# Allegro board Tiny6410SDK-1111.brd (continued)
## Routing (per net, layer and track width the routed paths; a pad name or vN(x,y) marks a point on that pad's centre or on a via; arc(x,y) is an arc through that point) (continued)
TXD2: length 230.1
  TOP w0.203: v1(78.32,95.63) 78.87,95.08 79.96,95.08 80.84,94.2 96.62,94.2 99.95,97.53 99.95,98.17 100.58,98.81 U1.10 ; v1(90.93,62.1) 89.87,62.1 89.77,62.2 71.75,62.2 66.06,67.89 26.09,67.89 24.31,66.12 20.21,66.12 15.75,61.65 15.75,60.25 TINY6410.B11 ; v1(78.87,86.23) 79.17,85.93 109.28,85.93 109.58,86.23 111.84,86.23 113.58,87.97 114.21,87.97 115.27,89.03 116.1,89.03 117.07,89.99 117.86,89.99 119,91.14 CON5.11
  BOTTOM w0.203: v1(90.93,62.1) 89.79,62.1 86,65.89 86,78.82 83.74,81.08 83.74,81.99 79.5,86.23 v1(78.87,86.23) 79.02,86.38 79.02,94.85 78.32,95.54 v1(78.32,95.63) 78.32,96.05 69.42,104.95 69.42,105.87 66.73,108.56 58.6,108.56 56.95,110.21 48.77,110.21 47.02,111.96 CON3.1
TXD3: length 169.2
  TOP w0.203: v1(90.93,61.05) 90.56,61.05 89.96,60.45 75.02,60.45 74.08,61.39 71.41,61.39 65.72,67.08 26.43,67.08 24.65,65.3 23.64,65.3 21.11,65.3 17.78,61.98 17.78,60.22 TINY6410.B13
  BOTTOM w0.203: CON4.1 35.97,112.27 42.3,105.94 64.8,105.94 66.22,104.53 66.22,87.96 83.19,70.99 83.19,67.56 89.14,61.6 89.14,61.11 89.53,60.72 90.23,60.72 90.56,61.05 v1(90.93,61.05)
USB_D+: length 50
  TOP w0.203: v1(110.11,51.26) 109.84,51.52 U6.6
  BOTTOM w0.203: v1(110.11,51.26) 110.72,51.87 111.13,51.87 113.54,54.28 113.54,66.43 108.41,71.56 108.41,85.8 112.01,89.41 112.01,92.84 111.35,93.5 CON5.4
USB_D-: length 46.4
  TOP w0.203: U6.5 109.96,52.17 v1(110.11,52.32)
  BOTTOM w0.203: CON5.3 111.38,91.12 111.38,89.53 107.95,86.11 107.95,71.37 113.09,66.24 113.09,54.43 110.99,52.32 v1(110.11,52.32)
USBDN: length 125.6
  TOP w0.203: TINY6410.A32 36.8,101.2 36.8,96.68 45.14,88.34 48.44,88.34 50.93,85.85 56.52,85.85 58.07,84.29 72.1,84.29 72.55,83.85 76.03,80.37 107.86,80.37 108.25,80.75 109.89,80.75 110.26,80.37 v1(110.24,79.79) ; v1(122.05,49) 122.02,49.02 121.03,49.02 120.93,48.92 R16.1
  BOTTOM w0.203: v1(110.24,79.79) 110.49,79.54 110.49,77.09 115.7,71.88 115.7,52.45 118.9,49.25 121.21,49.25 121.46,49 v1(122.05,49)
USBDP: length 125.3
  TOP w0.203: TINY6410.A34 37.2,101.2 37.2,96.85 45.3,88.75 48.61,88.75 51.1,86.26 56.68,86.26 58.24,84.7 72.27,84.7 72.83,84.14 76.2,80.77 107.7,80.77 108.08,81.15 110.06,81.15 110.55,80.66 110.79,80.65 110.89,80.65 110.93,80.6 111.18,80.33 v1(111.15,79.75) ; R17.1 120.93,50.01 121.28,49.66 121.79,49.66 v1(122.05,49.91)
  BOTTOM w0.203: v1(111.15,79.75) 111,79.6 111,77.16 116.1,72.05 116.1,52.62 119.07,49.66 121.21,49.66 121.46,49.91 v1(122.05,49.91)
USBH_D+: length 9
  TOP w0.203: U6.26 116.45,53.47 117.47,52.45 117.47,51.31 118.62,50.16 R17.2 R79.2 R54.1
USBH_D-: length 7.9
  TOP w0.203: R80.2 R16.2 119.35,48.67 117.07,50.95 117.07,52.1 116.34,52.82 U6.25
VCLK: length 192.2
  TOP w0.203: v1(126.62,69.47) 127.81,68.28 130.68,68.28 132.26,66.69 LCD1.36 ; LCD3.36 175.99,92.93 173.48,90.43 LCD2.36 168.57,90.43 167.57,91.43 160.46,91.43 159.9,90.86 149.99,90.86 146.99,87.86 130.73,87.86 126.49,83.62 125.92,83.62 125.77,83.46 123.6,83.46 122.86,82.73 v1(122.79,82.73) 122.53,82.47 115.3,82.47 111.57,78.74 76.91,78.74 71.76,83.89 41.99,83.89 29.02,96.86 29.02,103.02 TINY6410.A25
  BOTTOM w0.203: v1(122.79,82.73) 122.81,82.71 122.81,72.64 125.98,69.47 v1(126.62,69.47)
VD0: length 45
  TOP w0.203: LCD3.3 176.93,62.04 175.6,62.04 173.28,64.36 173.28,73.79 173.14,73.92 LCD2.3 165.11,73.92 159.69,68.5 149.71,68.5 148.77,67.56 LCD1.3
VD1: length 47.4
  TOP w0.203: LCD2.4 164.96,74.42 v1(164.7,74.68) 163.45,74.68 157.68,68.91 149.55,68.91 148.27,67.63 LCD1.4
  BOTTOM w0.203: v1(164.7,74.68) 164.7,72.94 175.99,61.65 LCD3.4
VD2: length 209.4
  TOP w0.203: v1(150.24,85.84) 150.24,85.83 148.41,85.83 147.92,85.34 132.97,85.34 128.07,80.44 117.14,80.44 113.41,76.71 76.07,76.71 70.92,81.86 39.94,81.86 24.49,97.31 24.49,101.51 TINY6410.A20 ; LCD1.5 147.77,68.01 149.25,69.49 150.77,69.49 v1(151,69.72) 151.28,70 158.01,70 163.83,75.82 v1(165.23,75.82) 166.12,74.92 LCD2.5
  BOTTOM w0.203: v1(151,69.72) 150.72,70 150.72,70.55 150.24,71.04 v1(150.24,85.84) ; v1(165.23,75.82) 165.48,75.56 165.48,73.15 174.62,64.01 176.3,64.01 177.33,62.98 LCD3.5
VD3: length 207
  TOP w0.203: LCD3.6 173.71,65.26 173.71,74.96 173.24,75.42 LCD2.6 166.66,75.42 165.61,76.48 163.47,76.48 157.4,70.41 150.32,70.41 v1(150.06,70.15) 149.32,70.15 147.27,68.1 LCD1.6 ; v1(149.48,85.09) 149.14,85.09 148.99,85.24 148.44,85.24 148.14,84.94 133.14,84.94 128.23,80.04 117.31,80.04 113.58,76.3 75.9,76.3 70.75,81.45 39.69,81.45 38.54,82.6 38.43,82.6 24.05,96.98 24.05,100.46 23.08,101.43 23.08,103.08 TINY6410.A19
  BOTTOM w0.203: v1(149.48,85.09) 149.73,84.84 149.73,70.48 v1(150.06,70.15)
VD4: length 209.5
  TOP w0.203: TINY6410.A18 22,96.75 36.55,82.19 38.37,82.19 39.52,81.04 70.58,81.04 75.73,75.9 113.75,75.9 117.48,79.63 128.4,79.63 133.31,84.53 148.31,84.53 148.36,84.58 v1(148.72,84.58) ; LCD1.7 146.77,68.53 v1(148.75,70.51) 149.05,70.82 156.92,70.82 163.12,77.01 v1(166.37,77.01) 167.46,75.92 LCD2.7
  BOTTOM w0.203: v1(166.37,77.01) 166.45,76.94 166.45,73.94 174.35,66.04 176.26,66.04 177.32,64.98 LCD3.7 ; v1(148.75,70.51) 148.75,70.85 149.28,71.37 149.28,84.02 v1(148.72,84.58)
VD5: length 212.1
  TOP w0.203: v1(147.57,83.06) 146.51,84.12 133.47,84.12 128.57,79.22 117.65,79.22 113.92,75.49 75.56,75.49 70.41,80.64 37.35,80.64 21.09,96.9 21.09,103.09 TINY6410.A17 ; LCD1.8 146.27,69.18 147.32,70.23 147.32,70.27 v1(147.35,70.3) 147.35,70.36 148.21,71.22 156.69,71.22 163.19,77.72 v1(164.62,77.72) 166.71,77.72 168.01,76.42 LCD2.8
  BOTTOM w0.203: v1(164.62,77.72) 164.72,77.72 165.91,76.53 165.91,73.61 174.54,64.98 LCD3.8 ; v1(147.35,70.3) 147.35,70.39 147.96,70.99 147.96,78.06 147.8,78.21 147.8,81.69 147.57,81.92 v1(147.57,83.06)
VD6: length 207.7
  TOP w0.203: v1(146.56,83.06) 145.9,83.72 133.64,83.72 128.74,78.82 117.82,78.82 114.09,75.08 75.39,75.08 70.25,80.23 36.99,80.23 20.29,96.93 20.29,101.71 TINY6410.A16 ; LCD1.9 145.77,69.95 v1(146.94,71.12) 147.45,71.63 156.34,71.63 163.09,78.38 166.98,78.38 v1(167.51,77.85) 168.44,76.92 LCD2.9
  BOTTOM w0.203: v1(146.94,71.12) 147.32,71.5 147.32,81.31 146.56,82.07 v1(146.56,83.06) ; v1(167.51,77.85) 174.57,70.79 174.57,69.07 175.6,68.04 176.26,68.04 177.32,66.98 LCD3.9
VD7: length 206.8
  TOP w0.203: LCD3.10 174.12,68.85 174.12,75.13 173.69,75.56 173.69,76.38 173.33,76.73 173.33,77.24 173.14,77.42 LCD2.10 168.96,77.42 167.41,78.97 162.53,78.97 155.7,72.14 146.71,72.14 v1(146.56,71.98) 145.27,70.69 LCD1.10 ; TINY6410.A15 19.09,103.09 19.09,101.29 19.53,100.84 19.53,96.8 36.51,79.82 70.08,79.82 75.23,74.68 114.25,74.68 117.99,78.41 128.91,78.41 133.3,82.8 145.16,82.8 v1(145.41,83.06)
  BOTTOM w0.203: v1(146.56,71.98) 146.56,81.11 145.41,82.25 v1(145.41,83.06)
VD8: length 49.2
  TOP w0.203: LCD1.12 144.27,71.06 145.85,72.64 155.64,72.64 162.37,79.38 168.06,79.38 168.64,78.8 170.05,78.8 170.24,78.61 170.6,78.61 170.78,78.42 LCD2.12 173.27,78.42 173.74,77.96 173.74,76.91 174.09,76.56 174.09,75.74 174.52,75.31 174.52,70.45 LCD3.12
VD9: length 52.1
  TOP w0.203: LCD3.13 177.05,70.04 175.6,70.04 174.93,70.71 174.93,75.49 174.5,75.92 174.5,76.73 174.14,77.09 174.14,78.36 173.58,78.92 LCD2.13 170.86,78.92 170.76,79.02 170.4,79.02 170.22,79.2 168.81,79.2 168.23,79.78 162.2,79.78 155.57,73.15 154.75,73.15 154.73,73.13 145.75,73.13 143.77,71.15 LCD1.13
VD10: length 199.7
  TOP w0.203: TINY6410.A14 18,101.58 19.05,100.53 19.05,96.52 36.15,79.42 69.91,79.42 75.06,74.27 114.6,74.27 118.33,78 134.87,78 135.51,78.64 140.01,78.64 140.32,78.33 141.22,78.33 141.46,78.57 v1(143.76,78.57) ; LCD1.14 143.27,71.59 143.92,72.24 v1(143.92,72.29) 145.16,73.53 154.56,73.53 161.21,80.19 168.4,80.19 168.98,79.61 170.39,79.61 170.57,79.42 LCD2.14 173.74,79.42 174.55,78.61 174.55,77.34 175.05,76.84 175.05,76.31 175.44,75.92 176.38,75.92 176.93,75.37 176.93,71.92 LCD3.14
  BOTTOM w0.203: v1(143.76,78.57) 144.02,78.32 144.02,72.39 v1(143.92,72.29)
VD11: length 206.8
  TOP w0.203: v1(142.8,77.17) 136.53,77.17 136.15,77.55 118.45,77.55 114.76,73.86 74.89,73.86 69.74,79.01 35.8,79.01 18.44,96.37 18.44,99.85 17.09,101.2 17.09,103.09 TINY6410.A13 ; LCD2.15 170.65,79.92 170.55,80.02 169.16,80.02 168.43,80.75 164.67,80.75 v1(164.57,80.85) 161.16,80.85 160.12,79.81 159.94,79.81 154.18,74.04 144.7,74.04 142.95,72.29 v1(142.93,72.29) 142.77,72.13 LCD1.15
  BOTTOM w0.203: v1(142.93,72.29) 142.98,72.29 143.38,72.69 143.38,76.44 142.8,77.02 v1(142.8,77.17) ; v1(164.57,80.85) 165.33,80.09 166.29,80.09 174.34,72.04 176.38,72.04 177.32,72.98 LCD3.15
VD12: length 202.3
  TOP w0.203: TINY6410.A12 16,96.14 33.54,78.6 69.57,78.6 74.72,73.46 114.93,73.46 118.62,77.14 135.98,77.14 136.36,76.76 142.13,76.76 v1(142.68,76.2) ; LCD1.16 142.26,67.54 142.24,67.56 142.24,72.8 142.65,73.2 v1(142.68,73.2) 144.03,74.55 154.11,74.55 161.1,81.53 v1(165.38,81.53) 165.55,81.36 168.46,81.36 169.39,80.42 LCD2.16
  BOTTOM w0.203: v1(165.38,81.53) 166.41,80.51 166.46,80.51 173.99,72.98 LCD3.16 ; v1(142.68,73.2) v1(142.68,76.2)
VD13: length 205.7
  TOP w0.203: v1(141.73,76.1) 141.48,76.35 136.09,76.35 135.71,76.73 118.78,76.73 115.1,73.05 74.55,73.05 69.4,78.2 32.93,78.2 15.09,96.04 15.09,103.09 TINY6410.A11 ; LCD1.17 141.76,73.59 v1(141.86,73.69) 141.86,73.74 142.65,74.52 143.09,74.52 143.63,75.06 154.04,75.06 161.31,82.32 167.25,82.32 v1(167.55,82.02) 167.62,82.02 167.75,81.89 168.5,81.89 169.47,80.92 LCD2.17
  BOTTOM w0.203: LCD3.17 177.98,74.98 176.92,73.92 175.72,73.92 175.05,74.59 175.05,74.59 167.62,82.02 v1(167.55,82.02) ; v1(141.86,73.69) 141.86,73.82 141.73,73.95 v1(141.73,76.1)
VD14: length 201.3
  TOP w0.203: TINY6410.A10 13.51,101.51 13.51,96.72 32.44,77.79 69.24,77.79 74.38,72.64 115.27,72.64 118.95,76.33 135.51,76.33 136.14,75.69 138.1,75.69 138.89,74.9 141.58,74.9 141.6,74.93 ; LCD2.18 169.65,81.42 168.28,82.8 v1(168.02,82.8) 167.89,82.93 159.13,82.93 151.74,75.54 143.53,75.54 142.92,74.93 141.6,74.93 ; LCD1.18 141.26,73.35 141.2,73.41 141.2,73.96 141.6,74.37 141.6,74.93
  BOTTOM w0.203: v1(168.02,82.8) 168.35,82.47 168.35,81.92 175.29,74.98 LCD3.18
VD15: length 204.2
  TOP w0.203: v1(139.19,75.56) 139.32,75.44 142.41,75.44 142.51,75.54 142.96,75.54 143.36,75.95 151.57,75.95 159.22,83.59 168.18,83.59 169.07,82.7 169.08,82.7 169.86,81.92 LCD2.19 173.09,81.92 174.98,80.04 174.98,78.52 175.58,77.93 177.1,77.93 177.37,77.66 177.37,77.6 LCD3.19 ; TINY6410.A9 13.09,103.09 13.09,96.13 31.83,77.39 69.07,77.39 74.22,72.24 74.55,72.24 115.44,72.24 119.12,75.92 135.2,75.92 135.92,75.21 137.64,75.21 138.81,74.04 v1(139.19,74.04) 140.34,74.04 140.76,73.61 LCD1.19
  BOTTOM w0.203: v1(139.19,75.56) 139.06,75.44 139.06,74.17 v1(139.19,74.04)
VD16: length 58
  TOP w0.203: LCD1.21 139.76,71.82 138.94,72.64 v1(138.94,73.15) ; LCD3.21 176.93,80.04 175.58,80.04 174.24,81.38 174.24,82.76 173.88,83.11 173.34,83.11 173.14,82.92 LCD2.21 170.49,82.92 170.33,83.08 169.26,83.08 168.26,84.08 157.83,84.08 151.57,77.83 139.34,77.83 v1(139.32,77.85)
  BOTTOM w0.203: v1(138.94,73.15) 138.94,73.28 138.3,73.91 138.3,76.83 v1(139.32,77.85)
VD17: length 64
  TOP w0.203: v1(140.59,78.99) 140.97,79.38 150.88,79.38 156.34,84.84 164.97,84.84 v1(165.1,84.96) 165.57,84.49 168.43,84.49 169.43,83.49 170.5,83.49 170.56,83.42 LCD2.22 ; v1(137.92,73.28) 137.92,73.03 139.26,71.68 LCD1.22
  BOTTOM w0.203: v1(140.59,78.99) 140.13,78.99 139.85,78.71 139.17,78.71 137.85,77.39 137.85,73.36 v1(137.92,73.28) ; v1(165.1,84.96) 165.74,84.33 170.69,84.33 175.99,79.02 LCD3.22
VD18: length 209.7
  TOP w0.203: LCD1.23 138.76,71.42 136.65,73.53 v1(136.65,73.66) 136.14,73.66 135.6,74.2 134.78,74.2 134.05,74.93 133.8,75.18 130.31,75.18 129.98,75.51 124.59,75.51 124.21,75.13 118.91,75.13 115.1,71.32 74.56,71.32 68.9,76.98 31.2,76.98 11.56,96.62 11.56,101.56 TINY6410.A8 ; LCD2.23 169.57,83.92 168.6,84.9 168.49,84.92 168.34,85.08 166.55,85.08 166.42,85.22 v1(165.99,85.22) 165.58,85.62 156.55,85.62 150.73,79.81 140,79.81 v1(139.57,79.38)
  BOTTOM w0.203: v1(139.57,79.38) 139.21,79.38 136.4,76.56 136.4,73.91 v1(136.65,73.66) ; LCD3.23 177.05,81.92 175.51,81.92 174.25,83.18 172.46,83.18 170.8,84.84 166.37,84.84 v1(165.99,85.22)
VD19: length 207.9
  TOP w0.203: v1(136.6,79.45) 137.36,80.21 150.56,80.21 156.38,86.03 166.18,86.03 166.72,85.49 168.58,85.49 169.64,84.42 LCD2.24 173.06,84.42 173.96,83.52 174.05,83.52 174.65,82.93 174.65,82.32 LCD3.24 ; TINY6410.A7 11.09,103.09 11.09,96.1 30.73,76.45 68.85,76.45 74.39,70.92 115.27,70.92 119.05,74.7 124.35,74.7 124.43,74.78 133.63,74.78 134.62,73.79 135.38,73.79 v1(137.41,71.75) 138.26,70.91 LCD1.24
  BOTTOM w0.203: v1(136.6,79.45) 136.6,78.82 135.84,78.05 135.84,73.33 v1(137.41,71.75)
VD20: length 208.1
  TOP w0.203: v1(134.75,78.99) 136.37,80.62 150.4,80.62 156.21,86.44 166.35,86.44 166.89,85.89 168.75,85.89 169.72,84.92 LCD2.25 173.15,84.92 174.14,83.93 174.22,83.93 175.05,83.1 175.05,82.59 175.6,82.04 176.38,82.04 176.38,82.04 177.05,82.04 LCD3.25 ; LCD1.25 137.76,70.39 v1(135.13,73.03) 134.62,73.03 133.27,74.37 124.6,74.37 124.52,74.3 119.22,74.3 115.44,70.51 74.22,70.51 68.68,76.05 30.38,76.05 9.68,96.75 9.68,101.68 TINY6410.A6
  BOTTOM w0.203: v1(134.75,78.99) 134.75,78.74 134.24,78.23 134.24,73.91 v1(135.13,73.03)
VD21: length 210.4
  TOP w0.203: LCD3.26 175.21,83.76 175.21,83.86 173.8,85.27 173.38,85.27 173.22,85.43 LCD2.26 169.79,85.43 168.92,86.3 167.06,86.3 166.52,86.84 156.04,86.84 150.23,81.03 135.64,81.03 v1(133.86,79.25) ; TINY6410.A5 9.09,103.09 9.09,96.32 29.84,75.56 68.59,75.56 74.05,70.1 115.6,70.1 119.39,73.89 124.69,73.89 124.77,73.96 133.05,73.96 v1(135.51,71.5) 137.26,69.75 LCD1.26
  BOTTOM w0.203: v1(135.51,71.5) 133.73,73.28 133.73,79.12 v1(133.86,79.25)
VD22: length 211.6
  TOP w0.203: LCD3.27 177.05,84.04 175.6,84.04 173.97,85.67 173.55,85.67 173.3,85.93 LCD2.27 169.87,85.93 169.09,86.71 167.23,86.71 166.68,87.25 155.88,87.25 150.11,81.48 134.19,81.48 133.1,80.39 133.1,79.72 v1(133.05,79.68) ; LCD1.27 136.76,69.12 134.12,71.75 v1(134.11,71.75) 132.31,73.56 124.94,73.56 124.86,73.48 119.56,73.48 115.77,69.7 73.88,69.7 68.42,75.16 29.24,75.16 7.67,96.72 7.67,100.89 8,101.22 TINY6410.A4
  BOTTOM w0.203: v1(133.05,79.68) 133.05,79.61 132.94,79.5 132.94,72.94 134.11,71.77 v1(134.11,71.75)
VD23: length 213.8
  TOP w0.203: LCD1.28 136.26,68.59 v1(134.37,70.48) 131.7,73.15 130.47,73.15 130.39,73.08 119.73,73.08 115.94,69.29 73.71,69.29 68.3,74.7 28.8,74.7 7.08,96.42 7.08,103.08 TINY6410.A3 ; v1(132.08,79.12) 132.08,79.95 134.02,81.89 149.94,81.89 155.71,87.66 166.85,87.66 167.4,87.11 169.25,87.11 169.94,86.43 LCD2.28 173.37,86.43 173.72,86.08 174.89,86.08 LCD3.28
  BOTTOM w0.203: v1(132.08,79.12) 132.28,78.92 132.28,72.57 v1(134.37,70.48)
VDEN: length 195.3
  TOP w0.203: LCD3.33 177.03,90.02 175.51,90.02 174.42,88.93 LCD2.33 168.35,88.93 167.33,89.94 161.04,89.94 160.74,89.64 151.37,89.64 151.13,89.41 150.62,89.41 v1(150.37,89.15) ; LCD1.33 133.76,66.92 130.27,70.41 129.24,70.41 v1(128.68,70.97) ; TINY6410.A21 25.02,103.02 25.02,97.66 40.42,82.26 71.09,82.26 76.24,77.11 112.24,77.11 115.97,80.85 127.3,80.85 v1(127.56,81.1) 127.97,81.1 128.73,81.86 128.77,81.86 132.73,85.83 147.83,85.83 148.75,86.74 v1(150.37,86.74)
  BOTTOM w0.203: v1(150.37,86.74) v1(150.37,89.15) ; v1(127.56,81.1) 127.56,72.01 128.6,70.97 v1(128.68,70.97)
VSYNC: length 191.1
  TOP w0.203: LCD1.34 133.26,66.84 130.26,69.85 v1(128.65,69.85) ; TINY6410.A23 27.02,103.02 27.02,97.19 41.13,83.08 71.43,83.08 76.57,77.93 111.9,77.93 115.64,81.66 125.48,81.66 125.73,81.92 v1(126.36,81.92) 126.36,82.17 126.95,82.76 126.95,82.85 127.71,83.61 127.71,83.64 131.11,87.05 147.33,87.05 150.09,89.81 150.22,89.81 150.46,90.05 160.49,90.05 160.86,90.43 167.42,90.43 168.42,89.43 LCD2.34 173.88,89.43 175.26,90.81 175.82,90.81 LCD3.34
  BOTTOM w0.203: v1(128.65,69.85) 127.91,70.59 127.91,70.89 126.72,72.09 126.72,81.56 v1(126.36,81.92)
WIFI_IO: length 120.1
  TOP w0.203: CON11.11 148.46,96.04 148.46,96.71 147.94,97.23 147.94,97.89 145.63,100.2 112.46,100.2 101.98,89.73 72.45,89.73 71.63,90.55 R18.1 70.27,89.8 68.05,89.8 65.93,91.92 55.14,91.92 48.39,98.68 47.8,98.68 46.84,99.64 45.72,99.64 45.09,100.28 45.09,103.08 TINY6410.A41
WIFI_PD: length 114.7
  TOP w0.203: CON11.12 148.88,97.5 148.35,98.03 148.35,98.06 145.77,100.63 112.31,100.63 101.82,90.14 74.2,90.14 72.26,92.08 R73.1 70.27,91.33 67.1,91.33 66.09,92.33 55.31,92.33 48.56,99.09 48.01,99.09 46.61,100.48 46.61,101.39 TINY6410.A42
X1: length 17.3
  TOP w0.254: 117.86,47.37 117.86,48.9 116.53,50.22 U6.21 ; 117.86,47.37 117.86,47.12 118.11,46.86 ; 117.86,47.37 118.11,47.12 118.11,46.86 ; Y1.2 126.25,47.64 123.42,44.81 120.31,44.81 119.52,45.59 C31.1 118.11,46.86
X2: length 15.5
  TOP w0.254: U6.20 116.2,49.57 116.64,49.13 116.64,49.1 117.22,48.51 117.22,46.37 118.87,44.72 118.87,44.07 C64.1 120.29,44.22 122.05,44.22 122.15,44.32 125.93,44.32 Y1.1

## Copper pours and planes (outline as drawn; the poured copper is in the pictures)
GND on TOP (solid shape): 38.85,22.48 38.86,22.48 38.88,22.47 38.9,22.45 38.91,22.43 38.91,22.34 37.82,21.25 37.82,18.64 32.67,13.49 25.87,13.49 24.85,14.51 30.23,14.51 30.23,17.56 26.67,17.56 26.67,14.51 24.85,14.51 24.79,14.57 24.79,19.91 24.79,19.93 24.8,19.96 24.82,19.99 24.84,20.01 24.87,20.03 24.9,20.04 24.93,20.04 24.97,20.03 25,20.01 25.01,20 25.91,19.1 36.7,19.1 37.11,19.51 37.11,22.42 37.11,22.43 37.12,22.45 37.14,22.47 37.16,22.48 37.17,22.48
GND on TOP (solid shape): 115.97,7.1 116.07,7.13 116.16,7.08 116.92,6.58 117.81,6.78 117.94,6.79 118.01,6.68 118.01,5.89 117.99,5.85 117.94,5.83 117.67,5.83 117.67,3.59 117.66,3.58 112.13,3.58 112.02,3.66 112.04,3.8 112.28,4.04 112.87,4.04 114.63,5.8 114.67,5.8
GND on TOP (solid shape): 135.84,16.24 135.95,16.19 136.06,16.16 136.16,16.07 136.11,15.94 135.94,15.23 136.57,14.86 136.58,14.86 136.61,14.85 137.39,14.08 137.39,13.59 137.31,13.47 137.17,13.5 136.18,13.86 135.32,13.28 135.17,13.21 135.08,13.34 135.08,15.54 135.78,16.24 135.82,16.25
GND on TOP (solid shape): 112.78,11.91 112.79,11.89 113.63,11.16 114.69,11.47 114.83,11.5 114.91,11.38 114.91,10.49 114.99,10.41 114.99,8.54 114.9,8.42 114.76,8.45 112.89,8.31 113.63,6.59 113.73,6.5 113.69,6.37 112.43,5.11 111.84,5.11 111.81,5.07 111.74,5.06 111.7,5.12 111.7,5.83 111.42,5.83 111.37,5.85 111.35,5.89 111.35,8.96 108.59,11.73 108.57,11.76 108.57,11.8 108.62,11.91 108.65,11.93 112.75,11.93
GND on TOP (solid shape): 135.08,12.09 135.17,12.21 135.32,12.15 136.18,11.57 137.17,11.93 137.31,11.96 137.39,11.84 137.39,11.67 135.97,10.25 135.97,8.41 135.95,8.38 135.93,8.37 135.51,6.47 137.41,6.89 137.42,6.91 137.45,6.93 141.55,6.93 141.58,6.91 141.59,6.89 142.23,6.22 143.16,6.24 143.18,6.25 143.22,6.24 144.71,4.75 145.03,4.75 145.08,4.73 145.1,4.69 145.1,4.13 145.08,4.08 145.03,4.06 144.65,4.06 143.98,4.72 135.29,4.72 134.63,4.06 133.99,4.06 133.94,4.08 133.92,4.13 133.92,5.66 134.8,6.53 134.8,9.24 134.47,9.57 134.47,10.65 135.08,11.26
GND on TOP (solid shape): outline of 26657 points within 0.51,0.51 179.49,129.49
GND on TOP: 128.78,43.43 126.24,40.65 123.7,43.43 123.7,49.28 126.24,52.29 128.78,49.28
GND on TOP: 110.49,82.68 111.38,82.68 112.39,81.66 112.39,81.15 112.14,80.9 111.38,80.9 111,81.28 111,81.66 110.36,82.3 110.36,82.55
GND on BOTTOM: 83.5,38.93 83.69,38.73 83.69,30.73 81.66,28.7 78.36,28.7 77.85,28.19 77.85,25.4 75.69,23.24 72.26,23.24 70.1,25.4 70.1,28.96 71.63,30.48 77.85,30.48 78.99,29.34 80.64,29.34 81.28,29.97 81.28,34.16 80.26,35.18 80.26,37.47 81.72,38.93
GND_AC97 on TOP: 85.72,23.24 85.85,23.11 85.85,19.68 85.6,19.43 80.26,19.43 79.88,19.05 79.88,18.54 79.5,18.16 79.12,18.16 78.74,18.54 78.74,19.94 79.5,20.7 80.77,20.7 81.15,21.08 81.15,23.11 81.28,23.24
GND_AC97 on BOTTOM: 76.33,17.27 76.33,14.35 74.93,12.95 74.93,4.45 76.71,2.67 91.19,2.67 92.65,4.13 92.65,13.02 96.27,16.64 96.27,19.81 98.3,21.84 98.3,38.48 96.27,40.51 87.88,40.51 85.34,37.97 85.34,25.27 85.09,25.02 84.84,25.02 83.12,23.3 83.12,21.78 83.06,21.72 83.06,18.8 83.95,17.91 83.95,16.89 83.19,16.13 80.9,16.13 80.14,16.89 80.14,24 80.01,24.13 80.01,27.69 79.63,28.07 78.36,28.07 78.11,27.81 78.11,25.02 76.2,23.11 76.2,17.4
VDD5V on TOP: 31.11,25.65 32.51,25.65 32.77,25.4 32.77,22.35 33.02,22.1 36.45,22.1 36.7,21.84 36.7,20.07 36.2,19.56 26.29,19.56 23.11,22.73 18.92,22.73 18.29,23.37 18.29,25.53 19.05,26.29 30.48,26.29
VDD33V on TOP: 79.76,23.75 80.77,23.75 80.9,23.62 80.9,21.84 80.01,20.95 79.12,20.95 78.36,20.19 74.68,20.19 74.04,20.83 74.04,21.72 74.42,22.1 76.33,22.1 76.58,21.84 78.74,21.84 79.5,22.61 79.5,23.5
VDD_AC97 on TOP: 84.71,27.56 84.96,27.81 85.22,27.81 85.47,27.56 85.47,23.75 85.22,23.5 81.53,23.5 81.03,24 80.24,24 79.93,24.31 79.93,26.26 80.09,26.42 84.45,26.42 84.71,26.67
VDD_AC97 on BOTTOM: 90.68,25.15 92.58,27.05 92.58,34.42 90.81,36.2 90.17,36.2 90.17,35.05 90.68,34.54 90.68,27.69 89.79,26.8 81.79,26.8 81.53,26.54 81.53,25.4 81.79,25.15
(no net) on TOP: 179.49,4 178.42,1.48 175.87,0.51 4,0.51 1.53,1.54 0.51,4.01 0.51,126 1.53,128.47 4,129.49 176,129.49 178.47,128.46 179.49,125.99 ; 72 cut-outs
(no net) on BOTTOM: 179.49,4 178.42,1.48 175.87,0.51 4,0.51 1.53,1.54 0.51,4.01 0.51,126 1.53,128.47 4,129.49 176,129.49 178.47,128.46 179.49,125.99 ; 19 cut-outs

Small or netless copper shapes (teardrops, artwork), in the pictures only: 1 on TOP

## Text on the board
BOTTOM: buttom-layer2
TOP: top-layer1 | www.dianzi168.net
Ref Des/Silkscreen Top: S2 CONFIG | SD-BOOT | NAND | TV Out | B | L | OFF | ON | G | VIN | 5V | +5V | Tiny6410 | Tiny6410SDK | 1111 | SCON | SD WiFi
User.7: FIGURE | SIZE | 14.0 | 27.56 | 28.0 | 31.5 | 33.0 | 35.43 | 39.0 | 39.37 | 39.4 | 40.0 | 43.31 | 45.0 | 47.0 | 50.0 | 60.0 | 62.99 | 70.0 | 78.74 | 80.0 | 82.68 | 87.0 | 118.11 | 125.98 | 126.0 | 137.8 | 35.0 | 71.0 | 100.0 | 48.0x40.0 | DRILL CHART: TOP to BOTTOM | ALL UNITS ARE IN MILS | TOLERANCE | +0.0/-0.0 | +3.0/-3.0 | +2.99/-2.99 | +2.0/-0.0 | PLATED | NON-PLATED | QTY | 1145 | 1 | 2 | 77 | 12 | 120 | 3 | 14 | 4 | 11 | 36 | 6 | 27 | 10
